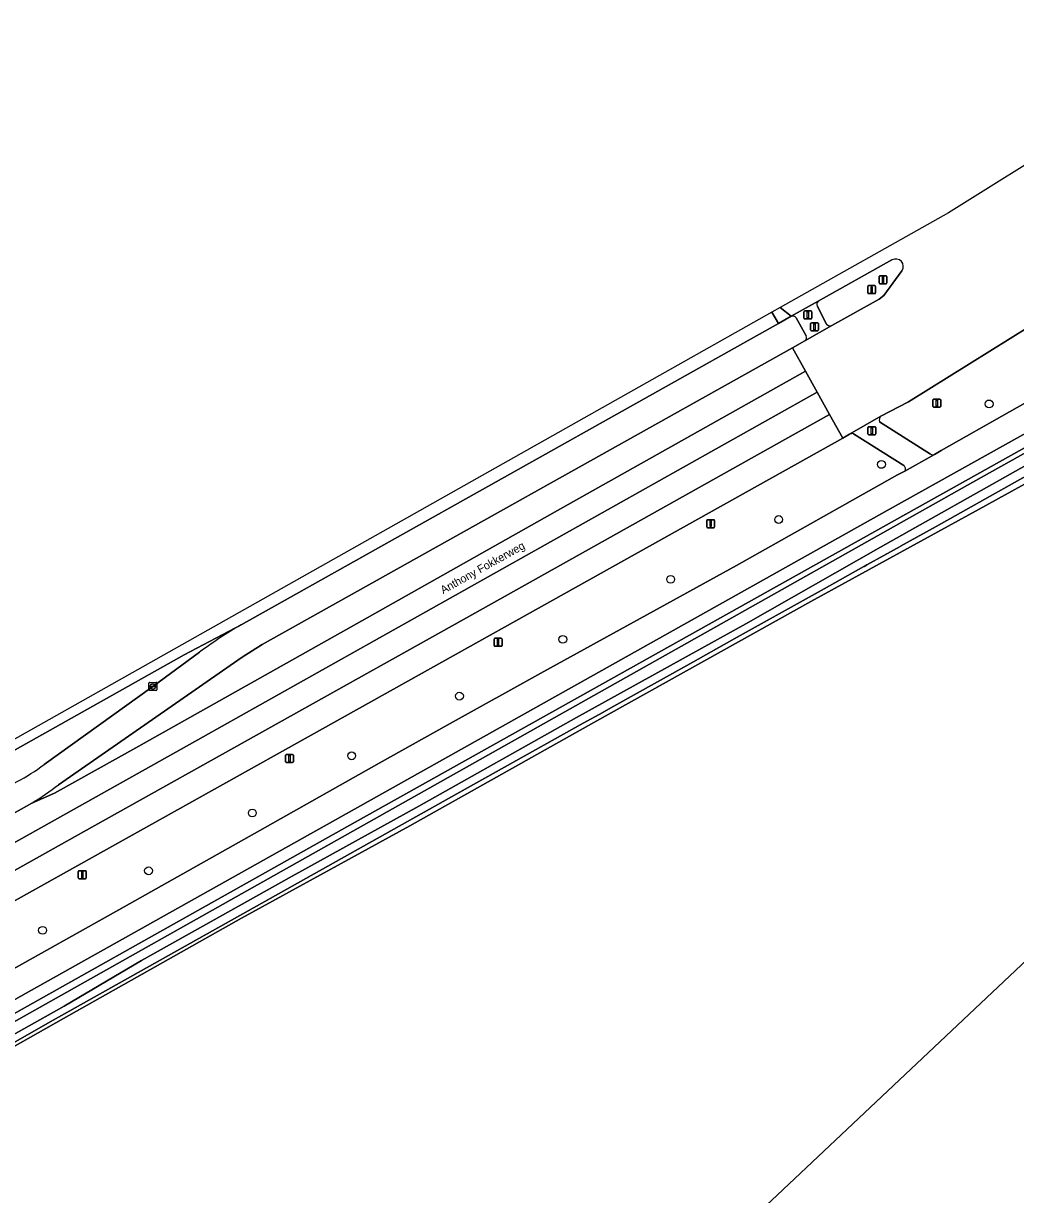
# Model space of a CAD drawing. Extents: x 157132 to 159279, y 384991 to 386650.
# Drawn here: x 157236.4 to 157360.5, y 386101 to 386247.3 of the extents above; entities that cross this region are included whole.
import ezdxf

# ---------------------------------------------------------------- set-up
doc = ezdxf.new("R2010")
doc.units = 0
for name, color, linetype in [('IMGEO_Berm_gesloten', 7, 'Continuous'), ('IMGEO_Berm_groen', 7, 'Continuous'), ('IMGEO_Boom', 7, 'Continuous'), ('IMGEO_Bouwland', 7, 'Continuous'), ('IMGEO_Fietspad_gesloten', 7, 'Continuous'), ('IMGEO_Fietspad_open', 7, 'Continuous'), ('IMGEO_Groenvoorziening', 7, 'Continuous'), ('IMGEO_Kolk', 7, 'Continuous'), ('IMGEO_Lichtmast', 7, 'Continuous'), ('IMGEO_Loofbos', 7, 'Continuous'), ('IMGEO_Oever', 7, 'Continuous'), ('IMGEO_Openbare_ruimte_label', 7, 'Continuous'), ('IMGEO_Portaal', 7, 'Continuous'), ('IMGEO_Rijbaan_regionaal_gesloten', 7, 'Continuous'), ('IMGEO_Verkeerseiland_open', 7, 'Continuous'), ('IMGEO_Verkeersregelinstallatiepaal', 7, 'Continuous'), ('IMGEO_Voetpad_open', 7, 'Continuous'), ('IMGEO_Waterloop', 7, 'Continuous')]:
    doc.layers.add(name, color=color, linetype=linetype)

msp = doc.modelspace()

# ---------------------------------------------------------------- linework, layer by layer
at = {"layer": 'IMGEO_Berm_gesloten'}
for points in [[(157332.43, 386210.73), (157330.82, 386209.82), (157263.65, 386172.17)], [(157334.28, 386208.3), (157333.04, 386210.54)], [(157263.78, 386168.11), (157266.27, 386169.72), (157332.58, 386206.81), (157334.12, 386207.67)], [(157258.46, 386168.76), (157252.62, 386164.46), (157239.03, 386154.7)], [(157240.83, 386152.18), (157263.78, 386168.11)], [(157163.23, 386108.2), (157237.49, 386149.89)]]:
    msp.add_lwpolyline(points, dxfattribs=at)
for centre, radius, start, end in [((157332.63, 386210.28), 0.484, 32.5209, 113.9937), ((157333.86, 386208.07), 0.477, 303.1806, 29.0462), ((157293.25, 386121.6), 58.6, 120.3446, 126.416), ((157224.65, 386173.86), 23.95, 297.316, 306.9042), ((157217.31, 386182.94), 38.72, 301.4069, 307.4017)]:
    msp.add_arc(centre, radius, start, end, dxfattribs=at)
at = {"layer": 'IMGEO_Berm_groen'}
for points in [[(157375.45, 386217.91), (157364.88, 386211.12), (157347.07, 386200.05)], [(157350.32, 386193.47), (157351.18, 386193.97), (157376.79, 386208.46)], [(157347.07, 386200.05), (157343.65, 386198.26)], [(157343.48, 386197.56), (157349.86, 386193.5)], [(157339.72, 386195.99), (157338.86, 386195.51), (157194.86, 386115.1), (157183.78, 386108.82)], [(157346.52, 386192.07), (157340.23, 386196.05)], [(157280.92, 386154.89), (157289.42, 386159.61), (157301.5, 386166.32), (157325.57, 386179.6), (157345.73, 386190.93), (157346.62, 386191.38)], [(157183.83, 386099.48), (157189.59, 386103.18), (157192.54, 386105.06), (157199.15, 386108.93), (157216.57, 386118.79), (157232.77, 386127.85), (157249.02, 386136.91), (157265.99, 386146.48), (157280.92, 386154.89)]]:
    msp.add_lwpolyline(points, dxfattribs=at)
for centre, radius, start, end in [((157344.03, 386197.79), 0.598, 129.3964, 202.7643), ((157340.1, 386195.09), 0.974, 82.0163, 112.7027), ((157350.12, 386193.89), 0.469, 236.3585, 295.7342), ((157346.25, 386191.68), 0.47, 321.1296, 55.9729)]:
    msp.add_arc(centre, radius, start, end, dxfattribs=at)
at = {"layer": 'IMGEO_Boom'}
for centre in [(157357.17, 386199.78), (157343.71, 386192.22), (157330.85, 386185.33), (157317.36, 386177.85), (157303.87, 386170.35), (157290.95, 386163.26), (157277.48, 386155.8), (157265.05, 386148.65), (157252.08, 386141.43), (157238.83, 386133.99)]:
    msp.add_circle(centre, 0.489, dxfattribs=at)
at = {"layer": 'IMGEO_Bouwland'}
for points in [[(157269.71, 386044.28), (157329.95, 386100.2), (157465.79, 386228.19), (157439.36, 386247.03), (157438.08, 386246.09), (157437.71, 386245.57), (157436.41, 386244.57), (157435.51, 386243.93), (157433.16, 386242.26), (157425.09, 386236.02), (157421.04, 386232.88), (157418.42, 386230.06), (157410.05, 386221.86), (157406.93, 386218.91), (157404.95, 386217.14)], [(157390.33, 386206.23), (157370.97, 386194.93), (157355.94, 386186.64), (157334.87, 386175.09), (157307.76, 386159.95), (157284.74, 386147.04), (157263.69, 386135.49), (157241.46, 386122.96), (157215.19, 386108.12), (157203.72, 386101.65), (157202.61, 386100.97)]]:
    msp.add_lwpolyline(points, dxfattribs=at)
at = {"layer": 'IMGEO_Fietspad_gesloten'}
for points in [[(157376.79, 386208.46), (157351.18, 386193.97), (157350.32, 386193.47), (157346.62, 386191.38), (157345.73, 386190.93), (157325.57, 386179.6), (157301.5, 386166.32), (157289.42, 386159.61), (157280.92, 386154.89), (157265.99, 386146.48), (157249.02, 386136.91), (157232.77, 386127.85), (157216.57, 386118.79), (157199.15, 386108.93), (157192.54, 386105.06), (157189.59, 386103.18), (157183.83, 386099.48), (157185.77, 386096.92), (157197.41, 386104.01), (157237.43, 386126.52)], [(157237.43, 386126.52), (157276.11, 386148.18), (157344.43, 386186.45), (157379.77, 386206.17)]]:
    msp.add_lwpolyline(points, dxfattribs=at)
at = {"layer": 'IMGEO_Fietspad_open'}
for points in [[(157335.78, 386212.61), (157332.43, 386210.73)], [(157336.85, 386209.75), (157335.66, 386212.04)], [(157333.04, 386210.54), (157334.28, 386208.3)], [(157334.12, 386207.67), (157337.5, 386209.59)], [(157343.65, 386198.26), (157339.72, 386195.99)], [(157349.86, 386193.5), (157343.48, 386197.56)], [(157340.23, 386196.05), (157346.52, 386192.07)], [(157346.62, 386191.38), (157350.32, 386193.47)]]:
    msp.add_lwpolyline(points, dxfattribs=at)
for centre, radius, start, end in [((157336.15, 386212.23), 0.525, 133.694, 201.4184), ((157332.63, 386210.28), 0.484, 32.5209, 113.9937), ((157337.28, 386210.07), 0.535, 217.4867, 294.815), ((157333.86, 386208.07), 0.477, 303.1806, 29.0462), ((157344.03, 386197.79), 0.598, 129.3964, 202.7643), ((157340.1, 386195.09), 0.974, 82.0163, 112.7027), ((157350.12, 386193.89), 0.469, 236.3585, 295.7342), ((157346.25, 386191.68), 0.47, 321.1296, 55.9729)]:
    msp.add_arc(centre, radius, start, end, dxfattribs=at)
at = {"layer": 'IMGEO_Groenvoorziening'}
msp.add_lwpolyline([(157380.46, 386204.84), (157345.32, 386185.22), (157276.87, 386146.91), (157238.29, 386125.27), (157199.17, 386103.32), (157200.73, 386103.12), (157355.13, 386190.01), (157382.1, 386205.07), (157393.88, 386212.34), (157399.91, 386217.07), (157403.65, 386220.37), (157419, 386234.87)], dxfattribs=at)
at = {"layer": 'IMGEO_Kolk'}
for p, q in [((157252.19, 386164.96), (157253.04, 386164.96)), ((157252.12, 386164.03), (157252.12, 386164.89)), ((157253.04, 386163.96), (157252.19, 386163.96)), ((157252.37, 386164.45), (157252.37, 386164.47)), ((157252.81, 386164.42), (157252.41, 386164.42)), ((157252.42, 386164.5), (157252.81, 386164.5)), ((157252.6, 386164.74), (157252.63, 386164.74)), ((157252.63, 386164.18), (157252.6, 386164.18)), ((157252.86, 386164.47), (157252.86, 386164.45)), ((157253.12, 386164.89), (157253.12, 386164.03))]:
    msp.add_line(p, q, dxfattribs=at)
for points in [[(157252.19, 386164.96), (157253.04, 386164.96)], [(157252.12, 386164.03), (157252.12, 386164.89)], [(157253.04, 386163.96), (157252.19, 386163.96)], [(157253.12, 386164.89), (157253.12, 386164.03)]]:
    msp.add_lwpolyline(points, dxfattribs=at)
for centre, radius, start, end in [((157252.19, 386164.89), 0.0765, 91.552, 178.448), ((157252.19, 386164.89), 0.0765, 91.552, 178.448), ((157253.04, 386164.89), 0.0765, 1.552, 88.448), ((157253.04, 386164.89), 0.0765, 1.552, 88.448), ((157252.19, 386164.04), 0.0765, 181.552, 268.448), ((157252.19, 386164.04), 0.0765, 181.552, 268.448), ((157252.41, 386164.46), 0.0403, 85.8775, 175.7526), ((157252.41, 386164.45), 0.0366, 178.938, 274.7102), ((157252.82, 386164.47), 0.0386, 1.7309, 96.639), ((157252.82, 386164.46), 0.043, 264.8664, 352.4533), ((157253.04, 386164.04), 0.0765, 271.552, 358.448), ((157253.04, 386164.04), 0.0765, 271.552, 358.448)]:
    msp.add_arc(centre, radius, start, end, dxfattribs=at)
for centre, major_axis, ratio, start_param, end_param in [((157252.6, 386164.46), (-0.387, 0.002), 0.722429, 4.712389, 7.853982), ((157252.63, 386164.46), (-0.39, 0.002), 0.717154, 1.570796, 4.712389)]:
    msp.add_ellipse(centre, major_axis=major_axis, ratio=ratio, start_param=start_param, end_param=end_param, dxfattribs=at)
at = {"layer": 'IMGEO_Lichtmast'}
for p, q in [((157343.41, 386214.9), (157343.41, 386215.69)), ((157343.41, 386215.69), (157343.41, 386214.9)), ((157343.51, 386215.79), (157344.3, 386215.79)), ((157344.3, 386215.79), (157343.51, 386215.79)), ((157344.3, 386214.8), (157343.51, 386214.8)), ((157343.51, 386214.8), (157344.3, 386214.8)), ((157344.4, 386215.69), (157344.4, 386214.9)), ((157344.4, 386214.9), (157344.4, 386215.69)), ((157321.86, 386184.41), (157321.86, 386185.21)), ((157321.86, 386185.21), (157321.86, 386184.41)), ((157321.96, 386185.31), (157322.75, 386185.31)), ((157322.75, 386185.31), (157321.96, 386185.31)), ((157322.75, 386184.31), (157321.96, 386184.31)), ((157321.96, 386184.31), (157322.75, 386184.31)), ((157322.85, 386185.21), (157322.85, 386184.41)), ((157322.85, 386184.41), (157322.85, 386185.21)), ((157295.28, 386169.59), (157295.28, 386170.39)), ((157295.28, 386170.39), (157295.28, 386169.59)), ((157295.38, 386170.49), (157296.17, 386170.49)), ((157296.17, 386170.49), (157295.38, 386170.49)), ((157296.17, 386169.49), (157295.38, 386169.49)), ((157295.38, 386169.49), (157296.17, 386169.49)), ((157296.27, 386170.39), (157296.27, 386169.59)), ((157296.27, 386169.59), (157296.27, 386170.39)), ((157269.2, 386155.06), (157269.2, 386155.86)), ((157269.2, 386155.86), (157269.2, 386155.06)), ((157269.3, 386155.96), (157270.09, 386155.96)), ((157270.09, 386155.96), (157269.3, 386155.96)), ((157270.09, 386154.96), (157269.3, 386154.96)), ((157269.3, 386154.96), (157270.09, 386154.96)), ((157270.19, 386155.86), (157270.19, 386155.06)), ((157270.19, 386155.06), (157270.19, 386155.86)), ((157243.3, 386140.54), (157243.3, 386141.34)), ((157243.3, 386141.34), (157243.3, 386140.54)), ((157243.4, 386141.44), (157244.19, 386141.44)), ((157244.19, 386141.44), (157243.4, 386141.44)), ((157244.19, 386140.44), (157243.4, 386140.44)), ((157243.4, 386140.44), (157244.19, 386140.44)), ((157244.29, 386141.34), (157244.29, 386140.54)), ((157244.29, 386140.54), (157244.29, 386141.34))]:
    msp.add_line(p, q, dxfattribs=at)
for points in [[(157343.83, 386215.67), (157343.98, 386215.67), (157343.98, 386214.92), (157343.83, 386214.92), (157343.83, 386215.67)], [(157322.28, 386185.19), (157322.43, 386185.19), (157322.43, 386184.44), (157322.28, 386184.44), (157322.28, 386185.19)], [(157295.7, 386170.37), (157295.85, 386170.37), (157295.85, 386169.62), (157295.7, 386169.62), (157295.7, 386170.37)], [(157269.62, 386155.83), (157269.77, 386155.83), (157269.77, 386155.08), (157269.62, 386155.08), (157269.62, 386155.83)], [(157243.72, 386141.31), (157243.87, 386141.31), (157243.87, 386140.56), (157243.72, 386140.56), (157243.72, 386141.31)]]:
    msp.add_lwpolyline(points, dxfattribs=at)
for centre, start, end in [((157343.51, 386215.69), 90, 180), ((157343.51, 386215.69), 90, 180), ((157343.51, 386214.9), 180, 270), ((157343.51, 386214.9), 180, 270), ((157344.3, 386215.69), 0, 90), ((157344.3, 386215.69), 360, 90), ((157344.3, 386214.9), 270, 0), ((157344.3, 386214.9), 270, 0), ((157321.96, 386185.21), 90, 180), ((157321.96, 386185.21), 90, 180), ((157321.96, 386184.41), 180, 270), ((157321.96, 386184.41), 180, 270), ((157322.75, 386185.21), 0, 90), ((157322.75, 386185.21), 360, 90), ((157322.75, 386184.41), 270, 0), ((157322.75, 386184.41), 270, 0), ((157295.38, 386170.39), 90, 180), ((157295.38, 386170.39), 90, 180), ((157295.38, 386169.59), 180, 270), ((157295.38, 386169.59), 180, 270), ((157296.17, 386170.39), 0, 90), ((157296.17, 386170.39), 360, 90), ((157296.17, 386169.59), 270, 0), ((157296.17, 386169.59), 270, 0), ((157269.3, 386155.86), 90, 180), ((157269.3, 386155.86), 90, 180), ((157269.3, 386155.06), 180, 270), ((157269.3, 386155.06), 180, 270), ((157270.09, 386155.86), 0, 90), ((157270.09, 386155.86), 360, 90), ((157270.09, 386155.06), 270, 0), ((157270.09, 386155.06), 270, 0), ((157243.4, 386141.34), 90, 180), ((157243.4, 386141.34), 90, 180), ((157243.4, 386140.54), 180, 270), ((157243.4, 386140.54), 180, 270), ((157244.19, 386141.34), 0, 90), ((157244.19, 386141.34), 360, 90), ((157244.19, 386140.54), 270, 0), ((157244.19, 386140.54), 270, 0)]:
    msp.add_arc(centre, 0.1, start, end, dxfattribs=at)
at = {"layer": 'IMGEO_Loofbos'}
msp.add_lwpolyline([(157465.79, 386228.19), (157329.95, 386100.2), (157269.71, 386044.28), (157283.14, 386034.3)], dxfattribs=at)
at = {"layer": 'IMGEO_Oever'}
for points in [[(157436.28, 386247.34), (157433.75, 386245.51), (157419, 386234.87), (157403.65, 386220.37), (157399.91, 386217.07), (157393.88, 386212.34), (157382.1, 386205.07), (157355.13, 386190.01), (157200.73, 386103.12)], [(157201.18, 386101.43), (157202.96, 386102.52), (157212.1, 386107.78), (157227.68, 386116.76), (157241.55, 386124.52), (157251.2, 386130.23), (157270.05, 386140.77), (157285.86, 386149.52), (157305.57, 386160.6), (157326.74, 386172.3), (157343.57, 386181.89), (157361.8, 386192.13), (157380.17, 386202.19), (157390.14, 386207.76)], [(157202.61, 386100.97), (157203.72, 386101.65), (157215.19, 386108.12), (157241.46, 386122.96), (157263.69, 386135.49), (157284.74, 386147.04), (157307.76, 386159.95), (157334.87, 386175.09), (157355.94, 386186.64), (157370.97, 386194.93), (157390.33, 386206.23)], [(157365.75, 386192.98), (157350.53, 386184.48), (157346.08, 386182), (157346.04, 386181.98), (157343.99, 386180.83), (157341.88, 386179.66), (157341.53, 386179.46), (157341.51, 386179.45), (157336.56, 386176.68), (157325.68, 386170.61), (157320.14, 386167.52), (157315.72, 386165.05), (157310.25, 386162), (157308.4, 386160.97), (157306.41, 386159.86), (157291.66, 386151.62), (157240.15, 386122.76), (157227.09, 386115.36), (157223.24, 386113.18), (157223.23, 386113.17), (157222.82, 386112.94), (157206.44, 386103.66), (157201.54, 386100.81)]]:
    msp.add_lwpolyline(points, dxfattribs=at)
at = {"layer": 'IMGEO_Portaal'}
for p, q in [((157341.99, 386213.66), (157341.99, 386214.46)), ((157341.99, 386214.46), (157341.99, 386213.66)), ((157342.09, 386214.56), (157342.88, 386214.56)), ((157342.88, 386214.56), (157342.09, 386214.56)), ((157342.88, 386213.56), (157342.09, 386213.56)), ((157342.09, 386213.56), (157342.88, 386213.56)), ((157342.98, 386214.46), (157342.98, 386213.66)), ((157342.98, 386213.66), (157342.98, 386214.46)), ((157350.13, 386199.47), (157350.13, 386200.27)), ((157350.13, 386200.27), (157350.13, 386199.47)), ((157350.23, 386200.37), (157351.02, 386200.37)), ((157351.02, 386200.37), (157350.23, 386200.37)), ((157351.12, 386200.27), (157351.12, 386199.47)), ((157351.12, 386199.47), (157351.12, 386200.27)), ((157351.02, 386199.37), (157350.23, 386199.37)), ((157350.23, 386199.37), (157351.02, 386199.37))]:
    msp.add_line(p, q, dxfattribs=at)
for points in [[(157342.41, 386214.43), (157342.56, 386214.43), (157342.56, 386213.68), (157342.41, 386213.68), (157342.41, 386214.43)], [(157350.55, 386200.24), (157350.7, 386200.24), (157350.7, 386199.49), (157350.55, 386199.49), (157350.55, 386200.24)]]:
    msp.add_lwpolyline(points, dxfattribs=at)
for centre, start, end in [((157342.09, 386214.46), 90, 180), ((157342.09, 386214.46), 90, 180), ((157342.09, 386213.66), 180, 270), ((157342.09, 386213.66), 180, 270), ((157342.88, 386214.46), 0, 90), ((157342.88, 386214.46), 360, 90), ((157342.88, 386213.66), 270, 0), ((157342.88, 386213.66), 270, 0), ((157350.23, 386200.27), 90, 180), ((157350.23, 386200.27), 90, 180), ((157351.02, 386200.27), 0, 90), ((157351.02, 386200.27), 360, 90), ((157350.23, 386199.47), 180, 270), ((157350.23, 386199.47), 180, 270), ((157351.02, 386199.47), 270, 0), ((157351.02, 386199.47), 270, 0)]:
    msp.add_arc(centre, 0.1, start, end, dxfattribs=at)
at = {"layer": 'IMGEO_Rijbaan_regionaal_gesloten'}
for points in [[(157364.95, 386229.05), (157368.3, 386231.1), (157368.43, 386231.15), (157367.32, 386233.16), (157352.07, 386223.68), (157331.03, 386211.82)], [(157346.27, 386216.4), (157344.02, 386213.34), (157343.42, 386212.88), (157337.5, 386209.59), (157334.12, 386207.67), (157332.58, 386206.81), (157334.23, 386203.86), (157335.68, 386201.24), (157337.22, 386198.47), (157338.86, 386195.51), (157339.72, 386195.99), (157343.65, 386198.26), (157347.07, 386200.05), (157364.88, 386211.12), (157375.45, 386217.91), (157373.63, 386221.32), (157371.32, 386225.63), (157367.72, 386223.42)], [(157331.03, 386211.82), (157332.43, 386210.73), (157335.78, 386212.61), (157345.02, 386217.79)], [(157334.23, 386203.86), (157332.58, 386206.81), (157266.27, 386169.72), (157263.78, 386168.11), (157240.83, 386152.18)], [(157237.49, 386149.89), (157240.31, 386151.11), (157250.85, 386157.01), (157278.73, 386172.69), (157303.89, 386186.84), (157334.23, 386203.86)], [(157263.65, 386172.17), (157256.54, 386168.42), (157242.45, 386160.5), (157221.27, 386148.62), (157180.62, 386125.8), (157170.87, 386120.3), (157156.88, 386112.35), (157160.49, 386110.39), (157235.64, 386152.58)], [(157239.03, 386154.7), (157252.62, 386164.46), (157258.46, 386168.76)]]:
    msp.add_lwpolyline(points, dxfattribs=at)
for points in [[(157331.03, 386211.82), (157330.01, 386211.25), (157330.82, 386209.82), (157332.43, 386210.73)], [(157155.69, 386113.01), (157156.88, 386112.35), (157170.87, 386120.3), (157180.62, 386125.8), (157221.27, 386148.62), (157242.45, 386160.5), (157256.54, 386168.42), (157263.65, 386172.17), (157330.82, 386209.82), (157330.01, 386211.25)], [(157335.68, 386201.24), (157334.23, 386203.86), (157303.89, 386186.84), (157278.73, 386172.69), (157250.85, 386157.01), (157240.31, 386151.11), (157237.49, 386149.89), (157163.23, 386108.2), (157166.44, 386106.42), (157168.5, 386107.59), (157193.46, 386121.56), (157216.94, 386134.69), (157258.89, 386158.17), (157318.3, 386191.5)], [(157337.22, 386198.47), (157335.68, 386201.24), (157318.3, 386191.5), (157258.89, 386158.17), (157216.94, 386134.69), (157193.46, 386121.56), (157168.5, 386107.59), (157166.44, 386106.42), (157169.62, 386104.67), (157188.07, 386115.07), (157195.04, 386118.96), (157212.52, 386128.73), (157243.95, 386146.28), (157292.87, 386173.61), (157334.76, 386197.07)], [(157338.86, 386195.51), (157337.22, 386198.47), (157334.76, 386197.07), (157292.87, 386173.61), (157243.95, 386146.28), (157212.52, 386128.73), (157195.04, 386118.96), (157188.07, 386115.07), (157169.62, 386104.67), (157173.09, 386102.75), (157173.95, 386103.23), (157183.78, 386108.82), (157194.86, 386115.1)]]:
    msp.add_lwpolyline(points, close=True, dxfattribs=at)
for centre, radius, start, end in [((157345.48, 386216.94), 0.962, 325.8104, 118.0682), ((157293.25, 386121.6), 58.6, 120.3446, 126.416), ((157224.65, 386173.86), 23.95, 297.316, 306.9042), ((157217.31, 386182.94), 38.72, 301.4069, 307.4017)]:
    msp.add_arc(centre, radius, start, end, dxfattribs=at)
at = {"layer": 'IMGEO_Verkeerseiland_open'}
for points in [[(157345.02, 386217.79), (157335.78, 386212.61)], [(157343.42, 386212.88), (157344.02, 386213.34), (157346.27, 386216.4)], [(157335.66, 386212.04), (157336.85, 386209.75)], [(157337.5, 386209.59), (157343.42, 386212.88)]]:
    msp.add_lwpolyline(points, dxfattribs=at)
for centre, radius, start, end in [((157345.48, 386216.94), 0.962, 325.8104, 118.0682), ((157336.15, 386212.23), 0.525, 133.694, 201.4184), ((157337.28, 386210.07), 0.535, 217.4867, 294.815)]:
    msp.add_arc(centre, radius, start, end, dxfattribs=at)
at = {"layer": 'IMGEO_Verkeersregelinstallatiepaal'}
for p, q in [((157334.01, 386210.5), (157334.01, 386211.3)), ((157334.01, 386211.3), (157334.01, 386210.5)), ((157334.11, 386211.4), (157334.9, 386211.4)), ((157334.9, 386211.4), (157334.11, 386211.4)), ((157334.9, 386210.4), (157334.11, 386210.4)), ((157334.11, 386210.4), (157334.9, 386210.4)), ((157335, 386211.3), (157335, 386210.5)), ((157335, 386210.5), (157335, 386211.3)), ((157334.85, 386209.02), (157334.85, 386209.82)), ((157334.85, 386209.82), (157334.85, 386209.02)), ((157334.95, 386209.92), (157335.74, 386209.92)), ((157335.74, 386209.92), (157334.95, 386209.92)), ((157335.74, 386208.92), (157334.95, 386208.92)), ((157334.95, 386208.92), (157335.74, 386208.92)), ((157335.84, 386209.82), (157335.84, 386209.02)), ((157335.84, 386209.02), (157335.84, 386209.82)), ((157342.02, 386196.03), (157342.02, 386196.83)), ((157342.02, 386196.83), (157342.02, 386196.03)), ((157342.12, 386196.93), (157342.91, 386196.93)), ((157342.91, 386196.93), (157342.12, 386196.93)), ((157342.91, 386195.93), (157342.12, 386195.93)), ((157342.12, 386195.93), (157342.91, 386195.93)), ((157343.01, 386196.83), (157343.01, 386196.03)), ((157343.01, 386196.03), (157343.01, 386196.83))]:
    msp.add_line(p, q, dxfattribs=at)
for points in [[(157334.43, 386211.28), (157334.58, 386211.28), (157334.58, 386210.53), (157334.43, 386210.53), (157334.43, 386211.28)], [(157335.27, 386209.79), (157335.42, 386209.79), (157335.42, 386209.04), (157335.27, 386209.04), (157335.27, 386209.79)], [(157342.44, 386196.81), (157342.59, 386196.81), (157342.59, 386196.06), (157342.44, 386196.06), (157342.44, 386196.81)]]:
    msp.add_lwpolyline(points, dxfattribs=at)
for centre, start, end in [((157334.11, 386211.3), 90, 180), ((157334.11, 386211.3), 90, 180), ((157334.11, 386210.5), 180, 270), ((157334.11, 386210.5), 180, 270), ((157334.9, 386211.3), 0, 90), ((157334.9, 386211.3), 360, 90), ((157334.9, 386210.5), 270, 0), ((157334.9, 386210.5), 270, 0), ((157334.95, 386209.82), 90, 180), ((157334.95, 386209.82), 90, 180), ((157334.95, 386209.02), 180, 270), ((157334.95, 386209.02), 180, 270), ((157335.74, 386209.82), 0, 90), ((157335.74, 386209.82), 360, 90), ((157335.74, 386209.02), 270, 0), ((157335.74, 386209.02), 270, 0), ((157342.12, 386196.83), 90, 180), ((157342.12, 386196.83), 90, 180), ((157342.12, 386196.03), 180, 270), ((157342.12, 386196.03), 180, 270), ((157342.91, 386196.83), 0, 90), ((157342.91, 386196.83), 360, 90), ((157342.91, 386196.03), 270, 0), ((157342.91, 386196.03), 270, 0)]:
    msp.add_arc(centre, 0.1, start, end, dxfattribs=at)
at = {"layer": 'IMGEO_Voetpad_open'}
for points in [[(157379.77, 386206.17), (157344.43, 386186.45), (157276.11, 386148.18), (157237.43, 386126.52), (157197.41, 386104.01), (157185.77, 386096.92)], [(157186.83, 386095.78), (157199.08, 386103.27), (157199.17, 386103.32), (157238.29, 386125.27), (157276.87, 386146.91), (157345.32, 386185.22), (157380.46, 386204.84)]]:
    msp.add_lwpolyline(points, dxfattribs=at)
at = {"layer": 'IMGEO_Waterloop'}
for points in [[(157390.14, 386207.76), (157380.17, 386202.19), (157361.8, 386192.13), (157343.57, 386181.89), (157326.74, 386172.3), (157305.57, 386160.6), (157285.86, 386149.52), (157270.05, 386140.77), (157251.2, 386130.23), (157241.55, 386124.52), (157227.68, 386116.76), (157212.1, 386107.78), (157202.96, 386102.52), (157201.18, 386101.43)], [(157201.54, 386100.81), (157206.44, 386103.66), (157222.82, 386112.94), (157223.23, 386113.17), (157223.24, 386113.18), (157227.09, 386115.36), (157240.15, 386122.76), (157291.66, 386151.62), (157306.41, 386159.86), (157308.4, 386160.97), (157310.25, 386162), (157315.72, 386165.05), (157320.14, 386167.52), (157325.68, 386170.61), (157336.56, 386176.68), (157341.51, 386179.45), (157341.53, 386179.46), (157341.88, 386179.66), (157343.99, 386180.83), (157346.04, 386181.98), (157346.08, 386182), (157350.53, 386184.48), (157365.75, 386192.98)]]:
    msp.add_lwpolyline(points, dxfattribs=at)

# ---------------------------------------------------------------- texts
at = {"layer": 'IMGEO_Openbare_ruimte_label'}
msp.add_text('Anthony Fokkerweg', height=1, rotation=29.2048, dxfattribs=at).set_placement((157288.92, 386176))

doc.saveas('drawing.dxf')
